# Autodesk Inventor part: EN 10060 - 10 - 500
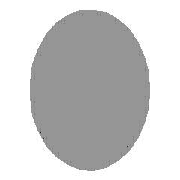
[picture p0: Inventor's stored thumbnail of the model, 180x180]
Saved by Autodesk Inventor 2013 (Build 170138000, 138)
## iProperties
Created: 2012-02
Part Number: EN 10060 - 10 - 500
Material: Stahl, weich
Description: Warmgewalzte Rundstähle
Document SubType Name: Modeling
Standard: DIN EN 10060
Designer: otto
Standard Revision: 2004
Standards Organization: DIN
Language: de-DE
Size Designation: 10 - 500
Categories: <MemberInstance><Categories><Category DisplayName="Profile" InternalName="089c4875-fa83-4c05-b084-43b9cc11f5ed" Mnemonic="GRDR"><CategoryParameter DisplayName="
Stock Number: 10
Density: 1 g/cm^3
IsCustomPart: 1
Author: otto
G_L: 500,000 mm
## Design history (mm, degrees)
node "Startebene"
node "Endebene"
sketch "Skizze"
  geometry: C1 r 5 at (0, 0)
  constraints: 1 centre point
  dimensions: "d0" = 10 diameter of C1 (= G_H)
extrude "Körper" new body sketch "Skizze" stored distance "d1" = 500 (= G_L); taper "d2" = 0 deg
node "Driven Length"
  sketch "Sketch3"
    geometry: L1 (0, 0)-(10, 0) reference
    constraints: 2 end point, 1 horizontal
  workplane "Work Plane3"
  sketch "Sketch4"
    geometry: L1 (-2, 0)-(12, 0) reference; L2 (-2, 500)-(12, 500) reference
    dimensions: "d8" = 500 distance between parallel lines of L1 L2 (derived)
body "Solid1"
other parameters: "G_H" = 10 [user parameter; used in 1 equation term], "G_L" = 500 (= d8) [user parameter; used in 1 equation term], "G_OFFSET_START" = 0 [user parameter; used in 1 equation term], "G_OFFSET_END" = 0 [user parameter; used in 1 equation term], "d4" = 0 (computed from G_OFFSET_START), "d7" = 90 deg, "MAS" = 61.7 [user parameter]
